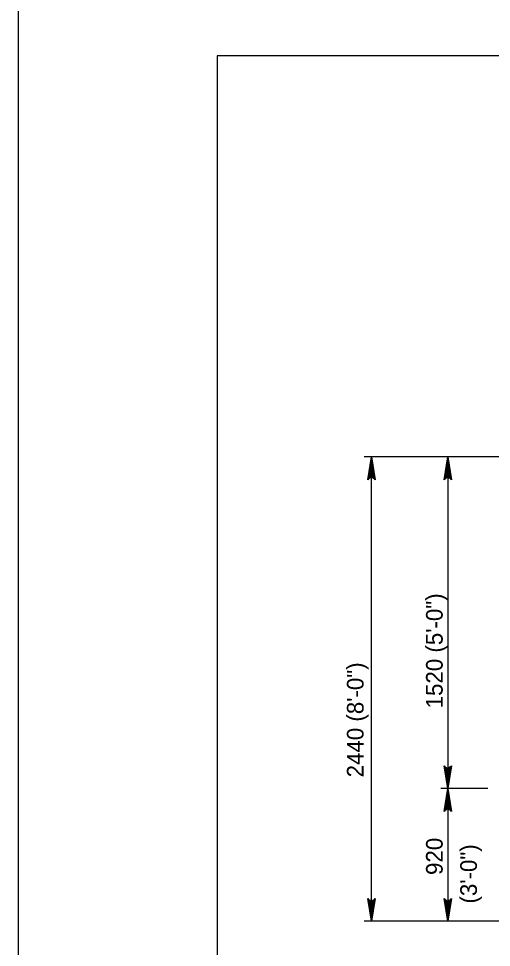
# Model space of a CAD drawing. Extents: x -4 to 901, y -468 to 720.
# Drawn here: x -3.7 to 91.5, y -68.7 to 118.5 of the extents above; entities that cross this region are included whole.
import ezdxf

# ---------------------------------------------------------------- set-up
doc = ezdxf.new("R2010")
doc.units = 0
for name, color, linetype in [('1', 7, 'Continuous'), ('2', 7, 'Continuous'), ('3', 7, 'Continuous'), ('PLT-BNDY', 7, 'Continuous')]:
    doc.layers.add(name, color=color, linetype=linetype)

msp = doc.modelspace()

# ---------------------------------------------------------------- linework, layer by layer
at = {"layer": '1'}
msp.add_lwpolyline([(822.258, -452.972125), (822.258, 111.027875), (36.258, 111.027875), (36.258, -452.972125), (822.258, -452.972125), (822.258, -426.613125), (622.258, -426.613125), (622.258, -361.935625), (822.258, -361.935625), (822.258, -332.972125), (622.258, -332.972125), (622.258, -452.972125), (701.0595, -452.972125), (701.0595, -426.613125), (701.0595, -452.972125), (778.0595, -452.972125), (778.0595, -426.613125), (778.0595, -438.929625), (822.258, -438.929625)], dxfattribs=at)
at = {"layer": '2'}
for p, q in [((110.55775, 30.163875), (65.93175, 30.163875)), ((67.37175, -63.436125), (67.37175, 30.163875)), ((82.76575, 30.163875), (82.76575, -36.690125)), ((90.82775, -36.690125), (81.32575, -36.690125)), ((82.76575, -36.690125), (82.76575, -63.436125)), ((120.15775, -63.436125), (65.93175, -63.436125))]:
    msp.add_line(p, q, dxfattribs=at)
for points in [[(66.82575, 25.803875), (67.14175, 25.965875), (67.37175, 30.163875), (66.82575, 25.803875), (66.63375, 25.579875), (67.37175, 30.163875), (67.57975, 25.969875), (67.89175, 25.815875), (67.37175, 30.163875), (68.09975, 25.579875), (67.89175, 25.815875)], [(82.21975, 25.803875), (82.53575, 25.965875), (82.76575, 30.163875), (82.21975, 25.803875), (82.02775, 25.579875), (82.76575, 30.163875), (82.97375, 25.969875), (83.28575, 25.815875), (82.76575, 30.163875), (83.49375, 25.579875), (83.28575, 25.815875)], [(83.31375, -32.332125), (82.99775, -32.494125), (82.76575, -36.690125), (83.31375, -32.332125), (83.50575, -32.108125), (82.76575, -36.690125), (82.55975, -32.496125), (82.24775, -32.344125), (82.76575, -36.690125), (82.03775, -32.108125), (82.24775, -32.344125)], [(82.21975, -41.050125), (82.53575, -40.886125), (82.76575, -36.690125), (82.21975, -41.050125), (82.02775, -41.272125), (82.76575, -36.690125), (82.97375, -40.884125), (83.28575, -41.036125), (82.76575, -36.690125), (83.49375, -41.272125), (83.28575, -41.036125)], [(67.91975, -59.078125), (67.60375, -59.240125), (67.37175, -63.436125), (67.91975, -59.078125), (68.11175, -58.854125), (67.37175, -63.436125), (67.16575, -59.244125), (66.85375, -59.090125), (67.37175, -63.436125), (66.64375, -58.854125), (66.85375, -59.090125)], [(83.31375, -59.078125), (82.99775, -59.240125), (82.76575, -63.436125), (83.31375, -59.078125), (83.50575, -58.854125), (82.76575, -63.436125), (82.55975, -59.244125), (82.24775, -59.090125), (82.76575, -63.436125), (82.03775, -58.854125), (82.24775, -59.090125)]]:
    msp.add_lwpolyline(points, dxfattribs=at)
at = {"layer": 'PLT-BNDY'}
msp.add_lwpolyline([(-3.742, 126.027875), (837.258, 126.027875), (837.258, -467.972125), (-3.742, -467.972125)], close=True, dxfattribs=at)

# ---------------------------------------------------------------- texts
at = {"layer": '3'}
for s, p in [('1520 (5\'-0")', (81.7275, -20.512375)), ('2440 (8\'-0")', (65.787, -34.426375)), ('920', (81.72575, -54.095375)), ('(3\'-0")', (88.624, -59.853625))]:
    msp.add_text(s, height=3.36, rotation=90, dxfattribs=at).set_placement(p)

doc.saveas('drawing.dxf')
